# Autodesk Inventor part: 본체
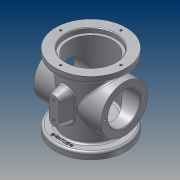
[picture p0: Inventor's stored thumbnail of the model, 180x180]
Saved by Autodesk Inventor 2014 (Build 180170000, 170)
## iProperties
Created: 2018-02
Part Number: 본체
Material: 알루미늄 6061
Document SubType Name: Modeling
Designer: user
Mass: 771.856 g
Surface Area: 821.825 cm^2
Volume: 284.818 cm^3
Density: 2.71 g/cm^3
Appearance: 알루미늄 - 평지
Author: user
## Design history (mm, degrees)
sketch "스케치1"
  geometry: C1 r 52.5 at (0, 0); 1 further point
  constraints: 1 centre point, 1 coincident
  dimensions: "d0" = 105 diameter of C1
extrude "돌출1" new body sketch "스케치1" distance "d1" = 10; taper "d2" = 0 deg
sketch "스케치2"
  geometry: C1 r 52.5 at (0, 0) reference; C2 r 38 at (0, 0)
  constraints: 1 centre point, 1 coincident
  dimensions: "d3" = 76 diameter of C2
extrude "돌출2" join sketch "스케치2" distance "d4" = 88; taper "d5" = 0 deg
sketch "스케치3"
  geometry: C1 r 38 at (0, 0) reference; C2 r 52.5 at (0, 0)
  constraints: 1 centre point, 1 coincident
  dimensions: "d6" = 105 diameter of C2
extrude "돌출3" join sketch "스케치3" distance "d7" = 10; taper "d8" = 0 deg
sketch "스케치4"
  geometry: C1 r 52.5 at (0, 0) reference; C2 r 34 at (0, 0)
  constraints: 1 centre point, 1 coincident
  dimensions: "d9" = 68 diameter of C2
extrude "돌출4" cut sketch "스케치4" distance "d10" = 16; taper "d11" = 0 deg
sketch "스케치5"
  geometry: C1 r 52.5 at (0, 0) reference; C2 r 37 at (0, 0)
  constraints: 1 centre point, 1 coincident
  dimensions: "d12" = 74 diameter of C2
extrude "돌출5" cut sketch "스케치5" distance "d13" = 7; taper "d14" = 0 deg
sketch "스케치9"
  geometry: L1 (52.5, 10)-(52.5, 0) reference; L2 (52.5, 0)-(34, 0) reference; L3 (34, 0)-(34, 16) reference; L4 (34, 16)-(-34, 16) reference; L5 (-37, 101)-(37, 101) reference; L6 (37, 101)-(37, 108) reference; L7 (37, 108)-(52.5, 108) reference; L8 (52.5, 108)-(52.5, 98) reference; L9 (52.5, 98)-(38, 98) reference; L10 (38, 98)-(38, 10) reference; L11 (38, 10)-(52.5, 10) reference; L12 (-52.5, 0)-(-52.5, 10) reference; L13 (-52.5, 10)-(-38, 10) reference; L14 (-38, 10)-(-38, 98) reference; L15 (-38, 98)-(-52.5, 98) reference; L16 (-52.5, 98)-(-52.5, 108) reference; L17 (-52.5, 108)-(-37, 108) reference; L18 (-37, 108)-(-37, 101) reference; L19 (-34, 16)-(-34, 0) reference; L20 (-34, 0)-(-52.5, 0) reference; L21 (-50, 89)-(50, 89); L22 (-50, 54)-(50, 54); L23 (-50, 89)-(-50, 54); L24 (50, 89)-(50, 54); 3 further points
  constraints: 8 end point, 2 midpoint, 2 parallel, 2 vertical alignment
  dimensions: "d24" = 100 distance of L21.start L21.end; "d25" = 100 distance of L22.start L22.end; "d26" = 54 vertical distance of L22.end point (0, 0); "d27" = 70 diameter of L21.end L22
revolve "회전1" sketch "스케치9" stored, may be unused: angle "d28" = 90 deg
sketch "스케치6"
  geometry: C1 r 37 at (0, 0) reference; C2 r 33 at (0, 0)
  constraints: 1 centre point, 1 coincident
  dimensions: "d15" = 66 diameter of C2
extrude "돌출6" cut sketch "스케치6" distance "d16" = 79; taper "d17" = 0 deg
sketch "스케치7"
  geometry: C1 r 33 at (0, 0) reference; C2 r 5 at (0, 0)
  constraints: 1 centre point, 1 coincident
  dimensions: "d18" = 10 diameter of C2
extrude "돌출7" cut sketch "스케치7" distance "d19" = 6; taper "d20" = 0 deg
sketch "스케치10"
  geometry: C1 r 35 at (0, 0) reference; C2 r 24 at (0, 0); 1 further point
  constraints: 1 centre point, 1 coincident
  dimensions: "d29" = 48 diameter of C2
extrude "돌출8" cut sketch "스케치10" distance "d30" = 148.75; taper "d31" = 0 deg
sketch "스케치11" dims "d32" = 58
  geometry: C1 r 24 at (0, 0) reference; C2 r 35 at (0, 0) reference; 6 further points
  constraints: 2 vertical alignment, 1 coincident, 7 other
  dimensions: "d35" = 360 deg dimension on point (0, 0) point (0, 29) (derived)
hole "구멍1" sketch "스케치11" at (0, 29), (-29, 0), (0, -29), (29, 0) diameter "d37" = 3.242; stored, may be unused: countersink angle "d41" = 90 deg, drill point angle "d43" = 118 deg; dims "d38" = 4, "d39" = 4, "d40" = 2, "d42" = 6
sketch "스케치12" dims "d44" = 90
  geometry: C1 r 37 at (0, 0) reference; C2 r 5 at (0, 0) reference; 5 further points
  constraints: 2 vertical alignment, 1 coincident, 7 other
  dimensions: "d47" = 360 deg dimension on point (0, 0) point (0, 45) (derived)
hole "구멍2" sketch "스케치12" at (0, 45), (-45, 0), (0, -45), (45, 0) diameter "d49" = 3.242; stored, may be unused: countersink angle "d53" = 90 deg, drill point angle "d55" = 118 deg; dims "d50" = 4, "d51" = 4, "d52" = 2, "d54" = 6
node "작업 평면1"
sketch "스케치13"
  geometry: L1 (0, 67)-(0, 41); L2 (7, 67)-(7, 41); L3 (-7, 41)-(-7, 67); L4 (50, 19)-(50, 89) reference; A1 r 7 centre (0, 67) between (7, 67) and (-7, 67); A2 r 7 centre (0, 41) between (-7, 41) and (7, 41); 3 further points
  constraints: 8 end point, 4 point on circle, 4 tangent, 2 centre point, 2 midpoint, 1 horizontal alignment, 1 parallel, 1 vertical
  dimensions: "d57" = 40 dimension on A2 A1; "d58" = 7 radius of A1; "d59" = 7 radius of A2 (derived); "d60" = 50 distance between parallel lines of L4 L1
extrude "돌출9" join sketch "스케치13" stored distance "d61" = 148.75; taper "d62" = 0 deg
feature "면 기울기1" dims angle "d63" = 15 deg
sketch "스케치14"
  geometry: A1 r 7 centre (0, 67) between (7, 67) and (-7, 67) reference; A2 r 7 centre (0, 41) between (-7, 41) and (7, 41) reference; 3 further points
  constraints: 2 coincident
hole "구멍3" sketch "스케치14" at (0, 67), (0, 41) diameter "d64" = 4.134; stored, may be unused: countersink angle "d68" = 90 deg, drill point angle "d70" = 118 deg; dims "d65" = 6, "d66" = 4, "d67" = 2, "d69" = 8
sketch "스케치15" dims "d71" = 86
  geometry: C1 r 38 at (0, 0) reference; C2 r 52.5 at (0, 0) reference; 2 further points
  constraints: 2 vertical alignment, 1 coincident, 3 other
feature "엠보싱1" sketch "스케치15" dims "d72" = 0.5, "d73" = 0
chamfer "모따기1" distance "d74" = 1; stored, may be unused: second distance "d75" = 2, angle "d76" = 45 deg
fillet "모깎기1" dims "d77" = 3
fillet "모깎기2" dims "d78" = 3
fillet "모깎기3" dims "d79" = 3
fillet "모깎기4" dims "d80" = 3
fillet "모깎기5" dims "d81" = 3
node "솔리드1"
mirror "대칭1"
node "절단 모서리 투영1"
other parameters: "d56" = 55
